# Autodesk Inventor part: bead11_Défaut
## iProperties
Shininess: 64.0
Length Units: 11269
Angle Units: 11279
Time Units: 11290
Mass Units: 11283
Length Display Precision: 3
Angle Display Precision: 2
Compacted: True
Part Number: bead11_Défaut
Document SubType Name: Modeling
Created: 2006-01
Material: Par défaut
Designer: Fricot
Density: 0.0
Volumn: 0.0
Area: 0.0
PropertySet Name: Model Information
Control State: 0
Master: False
Checked Out: False
Author: Fricot
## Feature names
1. Base1
